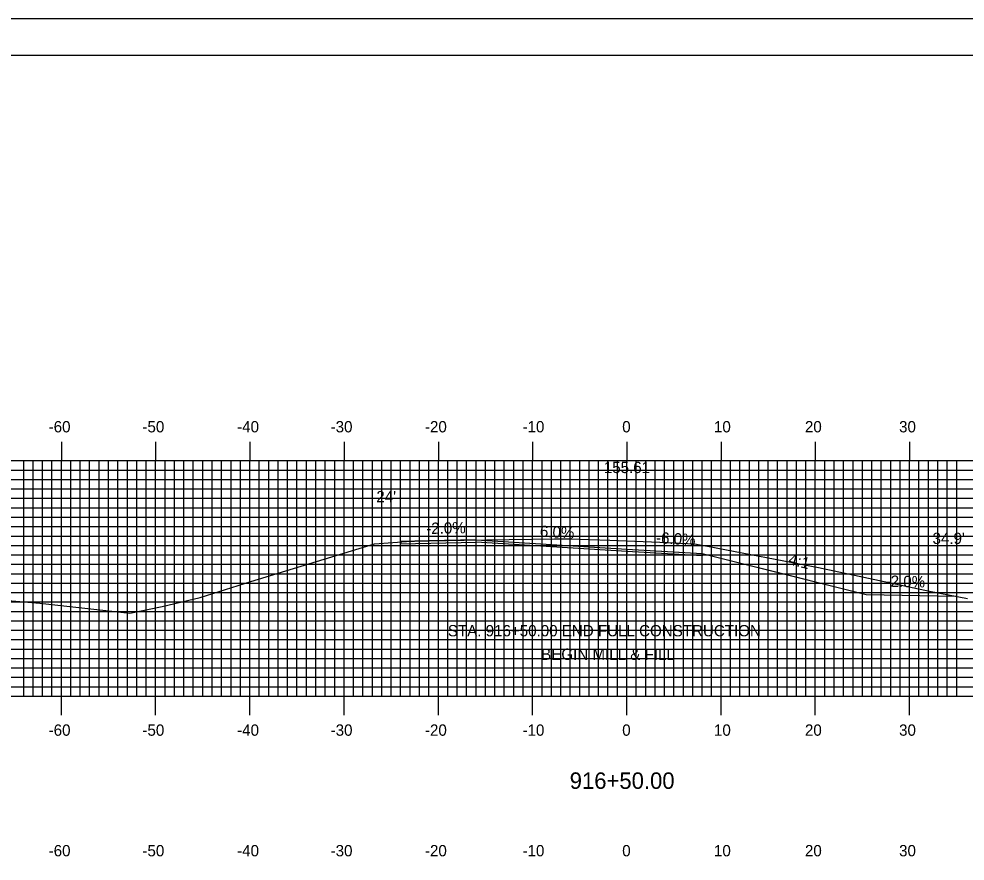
# Model space of a CAD drawing. Extents: x 861045 to 861388, y 364765 to 364985.
# Drawn here: x 861146.4 to 861246.8, y 364895.8 to 364985.2 of the extents above; entities that cross this region are included whole.
import ezdxf

# ---------------------------------------------------------------- set-up
doc = ezdxf.new("R2010")
doc.units = 0
for name, color, linetype in [('ANNOTATION', 7, 'Continuous'), ('BORDER', 7, 'Continuous'), ('D_Roadway_Centerline', 7, 'Continuous'), ('D_Roadway_Centerline_Text', 7, 'Continuous'), ('D_Roadway_Edge_Shoulder', 7, 'Continuous'), ('D_Roadway_Edge_TW', 7, 'Continuous'), ('D_Roadway_Pavement', 7, 'Continuous'), ('D_Roadway_SlopeLines', 7, 'Continuous'), ('D_Text_Standard', 7, 'Continuous'), ('H_V ANNOTATION', 7, 'Continuous'), ('M_Roadway_Centerline', 7, 'Continuous'), ('MAJOR', 7, 'Continuous'), ('MINOR', 7, 'Continuous'), ('PLOT BOUNDARY', 7, 'Continuous'), ('S_Roadway_Centerline', 7, 'Continuous')]:
    doc.layers.add(name, color=color, linetype=linetype)

msp = doc.modelspace()

# ---------------------------------------------------------------- linework, layer by layer
at = {"layer": 'BORDER'}
msp.add_lwpolyline([(861061.33, 364771.3), (861381.33, 364771.3), (861381.33, 364981.3), (861061.33, 364981.3)], close=True, dxfattribs=at)
at = {"layer": 'D_Roadway_Centerline'}
for points in [[(861186.93, 364929.72), (861189.92, 364929.78), (861189.93, 364929.78), (861193.67, 364929.86)], [(861213.4, 364928.77), (861218.92, 364928.44), (861218.93, 364928.44), (861218.93, 364928.44), (861230.28, 364925.61)]]:
    msp.add_lwpolyline(points, dxfattribs=at)
at = {"layer": 'D_Roadway_Edge_Shoulder'}
for points in [[(861194.93, 364929.88), (861189.93, 364929.78), (861186.93, 364929.72), (861186.93, 364929.47), (861194.93, 364929.63)], [(861210.93, 364928.92), (861218.93, 364928.44), (861218.93, 364928.19), (861210.93, 364928.67)]]:
    msp.add_lwpolyline(points, close=True, dxfattribs=at)
at = {"layer": 'D_Roadway_Edge_TW'}
msp.add_lwpolyline([(861194.93, 364929.88), (861210.93, 364928.92), (861210.93, 364928.67), (861194.93, 364929.63)], close=True, dxfattribs=at)
at = {"layer": 'D_Roadway_Pavement'}
msp.add_lwpolyline([(861210.93, 364928.67), (861210.93, 364928.42)], dxfattribs=at)
msp.add_lwpolyline([(861210.93, 364928.67), (861210.93, 364928.42)], dxfattribs=at)
at = {"layer": 'D_Roadway_SlopeLines'}
for points in [[(861218.93, 364928.44), (861236.32, 364924.09)], [(861236.32, 364924.09), (861245.83, 364923.9)]]:
    msp.add_lwpolyline(points, dxfattribs=at)
at = {"layer": 'MAJOR'}
for p, q in [((861150.93, 364940.31), (861150.93, 364938.3)), ((861160.93, 364940.31), (861160.93, 364938.3)), ((861170.93, 364940.31), (861170.93, 364938.3)), ((861180.93, 364940.31), (861180.93, 364938.3)), ((861190.93, 364940.31), (861190.93, 364938.3)), ((861200.93, 364940.31), (861200.93, 364938.3)), ((861210.93, 364940.31), (861210.93, 364938.3)), ((861220.93, 364940.31), (861220.93, 364938.3)), ((861230.93, 364940.31), (861230.93, 364938.3)), ((861240.93, 364940.31), (861240.93, 364938.3)), ((861070.93, 364938.3), (861350.93, 364938.3)), ((861070.93, 364938.3), (861350.93, 364938.3)), ((861070.93, 364938.3), (861350.93, 364938.3)), ((861150.93, 364913.3), (861150.93, 364938.3)), ((861150.93, 364913.3), (861150.93, 364938.3)), ((861160.93, 364913.3), (861160.93, 364938.3)), ((861160.93, 364913.3), (861160.93, 364938.3)), ((861170.93, 364913.3), (861170.93, 364938.3)), ((861170.93, 364913.3), (861170.93, 364938.3)), ((861180.93, 364913.3), (861180.93, 364938.3)), ((861180.93, 364913.3), (861180.93, 364938.3)), ((861190.93, 364913.3), (861190.93, 364938.3)), ((861190.93, 364913.3), (861190.93, 364938.3)), ((861200.93, 364913.3), (861200.93, 364938.3)), ((861200.93, 364913.3), (861200.93, 364938.3)), ((861210.93, 364913.3), (861210.93, 364938.3)), ((861210.93, 364913.3), (861210.93, 364938.3)), ((861220.93, 364913.3), (861220.93, 364938.3)), ((861220.93, 364913.3), (861220.93, 364938.3)), ((861230.93, 364913.3), (861230.93, 364938.3)), ((861230.93, 364913.3), (861230.93, 364938.3)), ((861240.93, 364913.3), (861240.93, 364938.3)), ((861240.93, 364913.3), (861240.93, 364938.3)), ((861070.93, 364933.3), (861350.93, 364933.3)), ((861070.93, 364933.3), (861350.93, 364933.3)), ((861070.93, 364928.3), (861350.93, 364928.3)), ((861070.93, 364928.3), (861350.93, 364928.3)), ((861070.93, 364923.3), (861350.93, 364923.3)), ((861070.93, 364923.3), (861350.93, 364923.3)), ((861070.93, 364918.3), (861350.93, 364918.3)), ((861070.93, 364918.3), (861350.93, 364918.3)), ((861070.93, 364913.3), (861350.93, 364913.3)), ((861070.93, 364913.3), (861350.93, 364913.3)), ((861070.93, 364913.3), (861350.93, 364913.3)), ((861150.93, 364911.3), (861150.93, 364913.3)), ((861160.93, 364911.3), (861160.93, 364913.3)), ((861170.93, 364911.3), (861170.93, 364913.3)), ((861180.93, 364911.3), (861180.93, 364913.3)), ((861190.93, 364911.3), (861190.93, 364913.3)), ((861200.93, 364911.3), (861200.93, 364913.3)), ((861210.93, 364911.3), (861210.93, 364913.3)), ((861220.93, 364911.3), (861220.93, 364913.3)), ((861230.93, 364911.3), (861230.93, 364913.3)), ((861240.93, 364911.3), (861240.93, 364913.3))]:
    msp.add_line(p, q, dxfattribs=at)
at = {"layer": 'MINOR'}
for p, q in [((861146.93, 364913.3), (861146.93, 364938.3)), ((861146.93, 364913.3), (861146.93, 364938.3)), ((861147.93, 364913.3), (861147.93, 364938.3)), ((861147.93, 364913.3), (861147.93, 364938.3)), ((861148.93, 364913.3), (861148.93, 364938.3)), ((861148.93, 364913.3), (861148.93, 364938.3)), ((861149.93, 364913.3), (861149.93, 364938.3)), ((861149.93, 364913.3), (861149.93, 364938.3)), ((861151.93, 364913.3), (861151.93, 364938.3)), ((861151.93, 364913.3), (861151.93, 364938.3)), ((861152.93, 364913.3), (861152.93, 364938.3)), ((861152.93, 364913.3), (861152.93, 364938.3)), ((861153.93, 364913.3), (861153.93, 364938.3)), ((861153.93, 364913.3), (861153.93, 364938.3)), ((861154.93, 364913.3), (861154.93, 364938.3)), ((861154.93, 364913.3), (861154.93, 364938.3)), ((861155.93, 364913.3), (861155.93, 364938.3)), ((861155.93, 364913.3), (861155.93, 364938.3)), ((861156.93, 364913.3), (861156.93, 364938.3)), ((861156.93, 364913.3), (861156.93, 364938.3)), ((861157.93, 364913.3), (861157.93, 364938.3)), ((861157.93, 364913.3), (861157.93, 364938.3)), ((861158.93, 364913.3), (861158.93, 364938.3)), ((861158.93, 364913.3), (861158.93, 364938.3)), ((861159.93, 364913.3), (861159.93, 364938.3)), ((861159.93, 364913.3), (861159.93, 364938.3)), ((861161.93, 364913.3), (861161.93, 364938.3)), ((861161.93, 364913.3), (861161.93, 364938.3)), ((861162.93, 364913.3), (861162.93, 364938.3)), ((861162.93, 364913.3), (861162.93, 364938.3)), ((861163.93, 364913.3), (861163.93, 364938.3)), ((861163.93, 364913.3), (861163.93, 364938.3)), ((861164.93, 364913.3), (861164.93, 364938.3)), ((861164.93, 364913.3), (861164.93, 364938.3)), ((861165.93, 364913.3), (861165.93, 364938.3)), ((861165.93, 364913.3), (861165.93, 364938.3)), ((861166.93, 364913.3), (861166.93, 364938.3)), ((861166.93, 364913.3), (861166.93, 364938.3)), ((861167.93, 364913.3), (861167.93, 364938.3)), ((861167.93, 364913.3), (861167.93, 364938.3)), ((861168.93, 364913.3), (861168.93, 364938.3)), ((861168.93, 364913.3), (861168.93, 364938.3)), ((861169.93, 364913.3), (861169.93, 364938.3)), ((861169.93, 364913.3), (861169.93, 364938.3)), ((861171.93, 364913.3), (861171.93, 364938.3)), ((861171.93, 364913.3), (861171.93, 364938.3)), ((861172.93, 364913.3), (861172.93, 364938.3)), ((861172.93, 364913.3), (861172.93, 364938.3)), ((861173.93, 364913.3), (861173.93, 364938.3)), ((861173.93, 364913.3), (861173.93, 364938.3)), ((861174.93, 364913.3), (861174.93, 364938.3)), ((861174.93, 364913.3), (861174.93, 364938.3)), ((861175.93, 364913.3), (861175.93, 364938.3)), ((861175.93, 364913.3), (861175.93, 364938.3)), ((861176.93, 364913.3), (861176.93, 364938.3)), ((861176.93, 364913.3), (861176.93, 364938.3)), ((861177.93, 364913.3), (861177.93, 364938.3)), ((861177.93, 364913.3), (861177.93, 364938.3)), ((861178.93, 364913.3), (861178.93, 364938.3)), ((861178.93, 364913.3), (861178.93, 364938.3)), ((861179.93, 364913.3), (861179.93, 364938.3)), ((861179.93, 364913.3), (861179.93, 364938.3)), ((861181.93, 364913.3), (861181.93, 364938.3)), ((861181.93, 364913.3), (861181.93, 364938.3)), ((861182.93, 364913.3), (861182.93, 364938.3)), ((861182.93, 364913.3), (861182.93, 364938.3)), ((861183.93, 364913.3), (861183.93, 364938.3)), ((861183.93, 364913.3), (861183.93, 364938.3)), ((861184.93, 364913.3), (861184.93, 364938.3)), ((861184.93, 364913.3), (861184.93, 364938.3)), ((861185.93, 364913.3), (861185.93, 364938.3)), ((861185.93, 364913.3), (861185.93, 364938.3)), ((861186.93, 364913.3), (861186.93, 364938.3)), ((861186.93, 364913.3), (861186.93, 364938.3)), ((861187.93, 364913.3), (861187.93, 364938.3)), ((861187.93, 364913.3), (861187.93, 364938.3)), ((861188.93, 364913.3), (861188.93, 364938.3)), ((861188.93, 364913.3), (861188.93, 364938.3)), ((861189.93, 364913.3), (861189.93, 364938.3)), ((861189.93, 364913.3), (861189.93, 364938.3)), ((861191.93, 364913.3), (861191.93, 364938.3)), ((861191.93, 364913.3), (861191.93, 364938.3)), ((861192.93, 364913.3), (861192.93, 364938.3)), ((861192.93, 364913.3), (861192.93, 364938.3)), ((861193.93, 364913.3), (861193.93, 364938.3)), ((861193.93, 364913.3), (861193.93, 364938.3)), ((861194.93, 364913.3), (861194.93, 364938.3)), ((861194.93, 364913.3), (861194.93, 364938.3)), ((861195.93, 364913.3), (861195.93, 364938.3)), ((861195.93, 364913.3), (861195.93, 364938.3)), ((861196.93, 364913.3), (861196.93, 364938.3)), ((861196.93, 364913.3), (861196.93, 364938.3)), ((861197.93, 364913.3), (861197.93, 364938.3)), ((861197.93, 364913.3), (861197.93, 364938.3)), ((861198.93, 364913.3), (861198.93, 364938.3)), ((861198.93, 364913.3), (861198.93, 364938.3)), ((861199.93, 364913.3), (861199.93, 364938.3)), ((861199.93, 364913.3), (861199.93, 364938.3)), ((861201.93, 364913.3), (861201.93, 364938.3)), ((861201.93, 364913.3), (861201.93, 364938.3)), ((861202.93, 364913.3), (861202.93, 364938.3)), ((861202.93, 364913.3), (861202.93, 364938.3)), ((861203.93, 364913.3), (861203.93, 364938.3)), ((861203.93, 364913.3), (861203.93, 364938.3)), ((861204.93, 364913.3), (861204.93, 364938.3)), ((861204.93, 364913.3), (861204.93, 364938.3)), ((861205.93, 364913.3), (861205.93, 364938.3)), ((861205.93, 364913.3), (861205.93, 364938.3)), ((861206.93, 364913.3), (861206.93, 364938.3)), ((861206.93, 364913.3), (861206.93, 364938.3)), ((861207.93, 364913.3), (861207.93, 364938.3)), ((861207.93, 364913.3), (861207.93, 364938.3)), ((861208.93, 364913.3), (861208.93, 364938.3)), ((861208.93, 364913.3), (861208.93, 364938.3)), ((861209.93, 364913.3), (861209.93, 364938.3)), ((861209.93, 364913.3), (861209.93, 364938.3)), ((861211.93, 364913.3), (861211.93, 364938.3)), ((861211.93, 364913.3), (861211.93, 364938.3)), ((861212.93, 364913.3), (861212.93, 364938.3)), ((861212.93, 364913.3), (861212.93, 364938.3)), ((861213.93, 364913.3), (861213.93, 364938.3)), ((861213.93, 364913.3), (861213.93, 364938.3)), ((861214.93, 364913.3), (861214.93, 364938.3)), ((861214.93, 364913.3), (861214.93, 364938.3)), ((861215.93, 364913.3), (861215.93, 364938.3)), ((861215.93, 364913.3), (861215.93, 364938.3)), ((861216.93, 364913.3), (861216.93, 364938.3)), ((861216.93, 364913.3), (861216.93, 364938.3)), ((861217.93, 364913.3), (861217.93, 364938.3)), ((861217.93, 364913.3), (861217.93, 364938.3)), ((861218.93, 364913.3), (861218.93, 364938.3)), ((861218.93, 364913.3), (861218.93, 364938.3)), ((861219.93, 364913.3), (861219.93, 364938.3)), ((861219.93, 364913.3), (861219.93, 364938.3)), ((861221.93, 364913.3), (861221.93, 364938.3)), ((861221.93, 364913.3), (861221.93, 364938.3)), ((861222.93, 364913.3), (861222.93, 364938.3)), ((861222.93, 364913.3), (861222.93, 364938.3)), ((861223.93, 364913.3), (861223.93, 364938.3)), ((861223.93, 364913.3), (861223.93, 364938.3)), ((861224.93, 364913.3), (861224.93, 364938.3)), ((861224.93, 364913.3), (861224.93, 364938.3)), ((861225.93, 364913.3), (861225.93, 364938.3)), ((861225.93, 364913.3), (861225.93, 364938.3)), ((861226.93, 364913.3), (861226.93, 364938.3)), ((861226.93, 364913.3), (861226.93, 364938.3)), ((861227.93, 364913.3), (861227.93, 364938.3)), ((861227.93, 364913.3), (861227.93, 364938.3)), ((861228.93, 364913.3), (861228.93, 364938.3)), ((861228.93, 364913.3), (861228.93, 364938.3)), ((861229.93, 364913.3), (861229.93, 364938.3)), ((861229.93, 364913.3), (861229.93, 364938.3)), ((861231.93, 364913.3), (861231.93, 364938.3)), ((861231.93, 364913.3), (861231.93, 364938.3)), ((861232.93, 364913.3), (861232.93, 364938.3)), ((861232.93, 364913.3), (861232.93, 364938.3)), ((861233.93, 364913.3), (861233.93, 364938.3)), ((861233.93, 364913.3), (861233.93, 364938.3)), ((861234.93, 364913.3), (861234.93, 364938.3)), ((861234.93, 364913.3), (861234.93, 364938.3)), ((861235.93, 364913.3), (861235.93, 364938.3)), ((861235.93, 364913.3), (861235.93, 364938.3)), ((861236.93, 364913.3), (861236.93, 364938.3)), ((861236.93, 364913.3), (861236.93, 364938.3)), ((861237.93, 364913.3), (861237.93, 364938.3)), ((861237.93, 364913.3), (861237.93, 364938.3)), ((861238.93, 364913.3), (861238.93, 364938.3)), ((861238.93, 364913.3), (861238.93, 364938.3)), ((861239.93, 364913.3), (861239.93, 364938.3)), ((861239.93, 364913.3), (861239.93, 364938.3)), ((861241.93, 364913.3), (861241.93, 364938.3)), ((861241.93, 364913.3), (861241.93, 364938.3)), ((861242.93, 364913.3), (861242.93, 364938.3)), ((861242.93, 364913.3), (861242.93, 364938.3)), ((861243.93, 364913.3), (861243.93, 364938.3)), ((861243.93, 364913.3), (861243.93, 364938.3)), ((861244.93, 364913.3), (861244.93, 364938.3)), ((861244.93, 364913.3), (861244.93, 364938.3)), ((861245.93, 364913.3), (861245.93, 364938.3)), ((861245.93, 364913.3), (861245.93, 364938.3)), ((861070.93, 364937.3), (861350.93, 364937.3)), ((861070.93, 364937.3), (861350.93, 364937.3)), ((861070.93, 364936.3), (861350.93, 364936.3)), ((861070.93, 364936.3), (861350.93, 364936.3)), ((861070.93, 364935.3), (861350.93, 364935.3)), ((861070.93, 364935.3), (861350.93, 364935.3)), ((861070.93, 364934.3), (861350.93, 364934.3)), ((861070.93, 364934.3), (861350.93, 364934.3)), ((861070.93, 364932.3), (861350.93, 364932.3)), ((861070.93, 364932.3), (861350.93, 364932.3)), ((861070.93, 364931.3), (861350.93, 364931.3)), ((861070.93, 364931.3), (861350.93, 364931.3)), ((861070.93, 364930.3), (861350.93, 364930.3)), ((861070.93, 364930.3), (861350.93, 364930.3)), ((861070.93, 364929.3), (861350.93, 364929.3)), ((861070.93, 364929.3), (861350.93, 364929.3)), ((861070.93, 364927.3), (861350.93, 364927.3)), ((861070.93, 364927.3), (861350.93, 364927.3)), ((861070.93, 364926.3), (861350.93, 364926.3)), ((861070.93, 364926.3), (861350.93, 364926.3)), ((861070.93, 364925.3), (861350.93, 364925.3)), ((861070.93, 364925.3), (861350.93, 364925.3)), ((861070.93, 364924.3), (861350.93, 364924.3)), ((861070.93, 364924.3), (861350.93, 364924.3)), ((861070.93, 364922.3), (861350.93, 364922.3)), ((861070.93, 364922.3), (861350.93, 364922.3)), ((861070.93, 364921.3), (861350.93, 364921.3)), ((861070.93, 364921.3), (861350.93, 364921.3)), ((861070.93, 364920.3), (861350.93, 364920.3)), ((861070.93, 364920.3), (861350.93, 364920.3)), ((861070.93, 364919.3), (861350.93, 364919.3)), ((861070.93, 364919.3), (861350.93, 364919.3)), ((861070.93, 364917.3), (861350.93, 364917.3)), ((861070.93, 364917.3), (861350.93, 364917.3)), ((861070.93, 364916.3), (861350.93, 364916.3)), ((861070.93, 364916.3), (861350.93, 364916.3)), ((861070.93, 364915.3), (861350.93, 364915.3)), ((861070.93, 364915.3), (861350.93, 364915.3)), ((861070.93, 364914.3), (861350.93, 364914.3)), ((861070.93, 364914.3), (861350.93, 364914.3))]:
    msp.add_line(p, q, dxfattribs=at)
at = {"layer": 'PLOT BOUNDARY'}
msp.add_lwpolyline([(861045.14, 364765.18), (861385.14, 364765.18), (861385.14, 364985.18), (861045.14, 364985.18)], close=True, dxfattribs=at)
at = {"layer": 'S_Roadway_Centerline'}
msp.add_lwpolyline([(861144.84, 364923.5), (861148.64, 364923.16), (861158.21, 364922.12), (861161.61, 364922.8), (861165.64, 364923.78), (861171.02, 364925.47), (861184.17, 364929.47), (861188.06, 364929.74), (861188.6, 364929.79), (861190.21, 364929.82), (861191.23, 364929.83), (861203.25, 364930.01), (861204.81, 364930), (861209.13, 364929.85), (861214.42, 364929.66), (861218.12, 364929.48), (861219.49, 364929.22), (861231.26, 364926.94), (861243.06, 364924.46), (861247.09, 364923.65)], dxfattribs=at)

# ---------------------------------------------------------------- texts
at = {"layer": 'ANNOTATION'}
for s, rotation, p in [('-2.0%', 1.1271, (861189.65, 364930.51)), ('6.0%', 356.8561, (861201.68, 364930.22)), ('-6.0%', 356.5662, (861214, 364929.54)), ('4:1', 345.9661, (861228, 364927.31)), ('-2.0%', 358.8634, (861238.38, 364924.92))]:
    msp.add_text(s, height=1.2, rotation=rotation, dxfattribs=at).set_placement(p)
at = {"layer": 'D_Roadway_Centerline_Text'}
msp.add_text('155.61', height=1.2, dxfattribs=at).set_placement((861208.49, 364936.98))
at = {"layer": 'D_Text_Standard'}
for s, p in [("24'", (861184.35, 364933.88)), ("34.9'", (861243.37, 364929.45)), ('STA. 916+50.00 END FULL CONSTRUCTION', (861191.94, 364919.65)), ('BEGIN MILL & FILL', (861201.84, 364917.15))]:
    msp.add_text(s, height=1.2, dxfattribs=at).set_placement(p)
at = {"layer": 'H_V ANNOTATION'}
for s, height, p in [('-60', 1.2, (861149.58, 364941.3)), ('-50', 1.2, (861159.53, 364941.3)), ('-40', 1.2, (861169.58, 364941.3)), ('-30', 1.2, (861179.5, 364941.3)), ('-20', 1.2, (861189.51, 364941.3)), ('-10', 1.2, (861199.86, 364941.3)), ('0', 1.2, (861210.44, 364941.3)), ('10', 1.2, (861220.18, 364941.3)), ('20', 1.2, (861229.83, 364941.3)), ('30', 1.2, (861239.82, 364941.3)), ('-60', 1.2, (861149.58, 364909.1)), ('-50', 1.2, (861159.53, 364909.1)), ('-40', 1.2, (861169.58, 364909.1)), ('-30', 1.2, (861179.5, 364909.1)), ('-20', 1.2, (861189.51, 364909.1)), ('-10', 1.2, (861199.86, 364909.1)), ('0', 1.2, (861210.44, 364909.1)), ('10', 1.2, (861220.18, 364909.1)), ('20', 1.2, (861229.83, 364909.1)), ('30', 1.2, (861239.82, 364909.1)), ('916+50.00', 1.75, (861204.87, 364903.46)), ('-60', 1.2, (861149.58, 364896.3)), ('-50', 1.2, (861159.53, 364896.3)), ('-40', 1.2, (861169.58, 364896.3)), ('-30', 1.2, (861179.5, 364896.3)), ('-20', 1.2, (861189.51, 364896.3)), ('-10', 1.2, (861199.86, 364896.3)), ('0', 1.2, (861210.44, 364896.3)), ('10', 1.2, (861220.18, 364896.3)), ('20', 1.2, (861229.83, 364896.3)), ('30', 1.2, (861239.82, 364896.3))]:
    msp.add_text(s, height=height, dxfattribs=at).set_placement(p)
at = {"layer": 'M_Roadway_Centerline'}
for s, p in [('C', (861204.8, 364930)), ('L', (861204.81, 364929.99))]:
    msp.add_text(s, height=0.0146, dxfattribs=at).set_placement(p)

doc.saveas('drawing.dxf')
